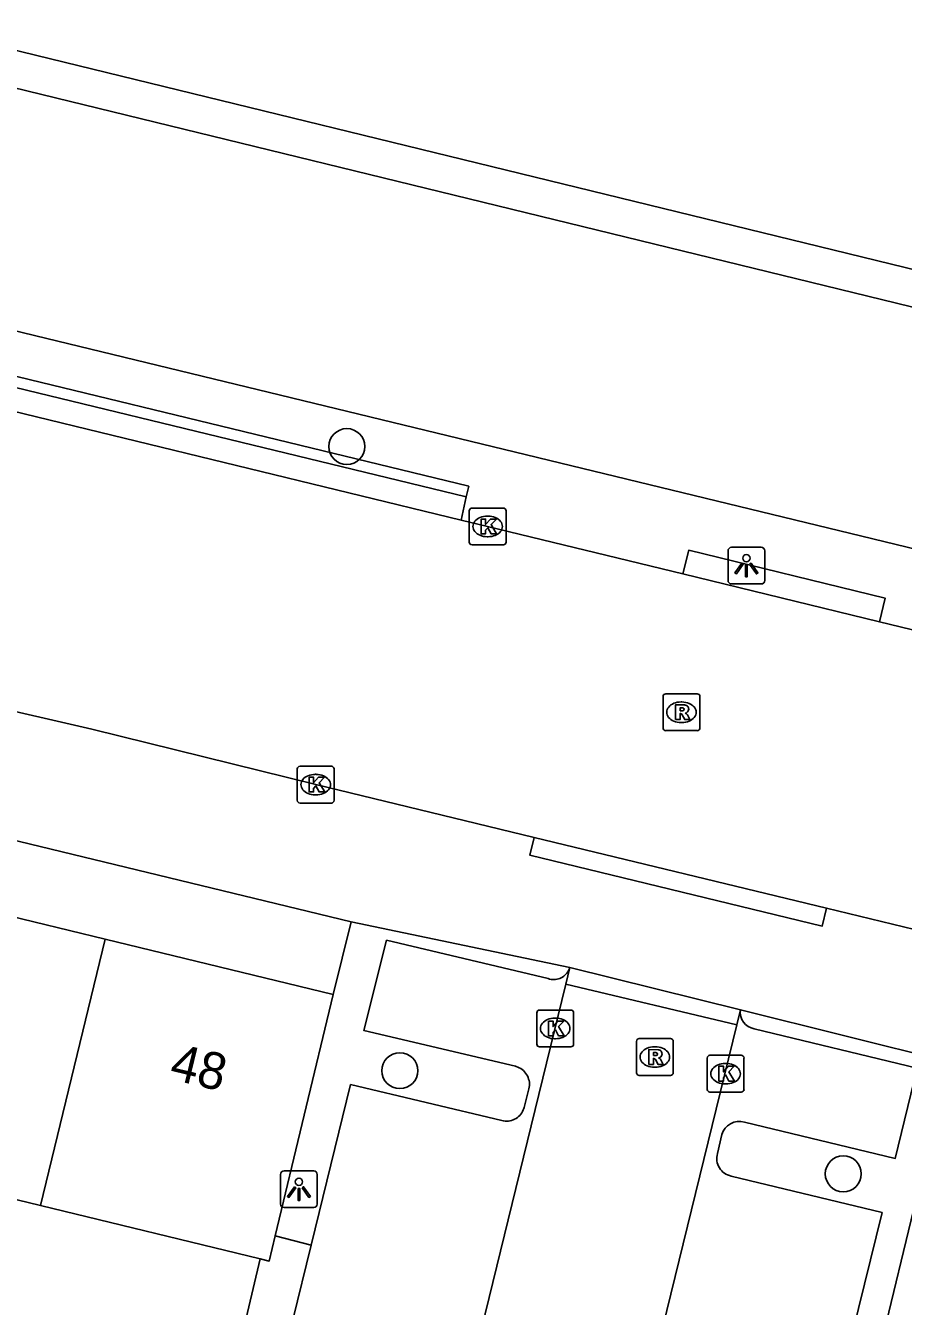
# Model space of a CAD drawing. Extents: x 162812 to 163818, y 381639 to 382470.
# Drawn here: x 163376.49 to 163400.35, y 382263.66 to 382298.47 of the extents above; entities that cross this region are included whole.
import ezdxf

# ---------------------------------------------------------------- set-up
doc = ezdxf.new("R2010")
doc.units = 0
for name, color, linetype in [('IMGEO_Boom', 7, 'Continuous'), ('IMGEO_Groenvoorziening', 7, 'Continuous'), ('IMGEO_Haag', 7, 'Continuous'), ('IMGEO_Kolk', 7, 'Continuous'), ('IMGEO_Lichtpunt', 7, 'Continuous'), ('IMGEO_Muur', 7, 'Continuous'), ('IMGEO_Pand', 7, 'Continuous'), ('IMGEO_Pand_nummerreeks', 7, 'Continuous'), ('IMGEO_Rijbaan_lokaal_gesloten', 7, 'Continuous'), ('IMGEO_Rijbaan_lokaal_open', 7, 'Continuous'), ('IMGEO_Rioolput', 7, 'Continuous'), ('IMGEO_Voetpad_open', 7, 'Continuous'), ('IMGEO_Waterloop', 7, 'Continuous')]:
    doc.layers.add(name, color=color, linetype=linetype)

msp = doc.modelspace()

# ---------------------------------------------------------------- linework, layer by layer
at = {"layer": 'IMGEO_Boom'}
for centre in [(163385.22, 382287.025), (163386.664, 382270.064), (163398.72, 382267.262)]:
    msp.add_circle(centre, 0.489, dxfattribs=at)
at = {"layer": 'IMGEO_Groenvoorziening'}
for points in [[(163321.09, 382310.224), (163499.763, 382266.618), (163515.133, 382262.867)], [(163454.527, 382271.183), (163319.582, 382303.902)], [(163388.463, 382285.657), (163388.534, 382285.949), (163352.363, 382294.719), (163352.293, 382294.427)], [(163399.704, 382282.265), (163399.86, 382282.905), (163394.518, 382284.21), (163394.36, 382283.564)]]:
    msp.add_lwpolyline(points, dxfattribs=at)
at = {"layer": 'IMGEO_Haag'}
for points in [[(163352.293, 382294.427), (163388.463, 382285.657)], [(163388.331, 382285.029), (163388.463, 382285.657)]]:
    msp.add_lwpolyline(points, dxfattribs=at)
at = {"layer": 'IMGEO_Kolk'}
for p, q in [((163388.625, 382285.355), (163389.477, 382285.355)), ((163388.55, 382284.429), (163388.55, 382285.281)), ((163389.038, 382285.135), (163389.063, 382285.135)), ((163389.551, 382285.281), (163389.551, 382284.429)), ((163389.477, 382284.355), (163388.625, 382284.355)), ((163389.061, 382284.575), (163389.036, 382284.575)), ((163383.874, 382277.412), (163383.874, 382278.264)), ((163383.949, 382278.338), (163384.801, 382278.338)), ((163384.362, 382278.118), (163384.387, 382278.118)), ((163384.875, 382278.264), (163384.875, 382277.412)), ((163384.801, 382277.338), (163383.949, 382277.338)), ((163384.385, 382277.558), (163384.36, 382277.558)), ((163390.386, 382270.786), (163390.386, 382271.638)), ((163390.461, 382271.712), (163391.313, 382271.712)), ((163390.874, 382271.492), (163390.899, 382271.492)), ((163391.387, 382271.638), (163391.387, 382270.786)), ((163391.313, 382270.712), (163390.461, 382270.712)), ((163390.897, 382270.932), (163390.872, 382270.932)), ((163395.019, 382269.556), (163395.019, 382270.408)), ((163395.094, 382270.482), (163395.946, 382270.482)), ((163396.02, 382270.408), (163396.02, 382269.556)), ((163395.507, 382270.262), (163395.532, 382270.262)), ((163395.53, 382269.702), (163395.505, 382269.702)), ((163395.946, 382269.482), (163395.094, 382269.482))]:
    msp.add_line(p, q, dxfattribs=at)
for points in [[(163388.625, 382285.355), (163389.477, 382285.355)], [(163388.55, 382284.429), (163388.55, 382285.281)], [(163388.871, 382285.055), (163388.994, 382285.055), (163388.994, 382284.904), (163389.124, 382285.055), (163389.288, 382285.055), (163389.142, 382284.904), (163389.295, 382284.655), (163389.143, 382284.655), (163389.058, 382284.819), (163388.994, 382284.752), (163388.994, 382284.655), (163388.871, 382284.655), (163388.871, 382285.055)], [(163389.551, 382285.281), (163389.551, 382284.429)], [(163389.477, 382284.355), (163388.625, 382284.355)], [(163383.874, 382277.412), (163383.874, 382278.264)], [(163383.949, 382278.338), (163384.801, 382278.338)], [(163384.195, 382278.038), (163384.318, 382278.038), (163384.318, 382277.887), (163384.448, 382278.038), (163384.612, 382278.038), (163384.466, 382277.887), (163384.619, 382277.638), (163384.467, 382277.638), (163384.382, 382277.802), (163384.318, 382277.735), (163384.318, 382277.638), (163384.195, 382277.638), (163384.195, 382278.038)], [(163384.875, 382278.264), (163384.875, 382277.412)], [(163384.801, 382277.338), (163383.949, 382277.338)], [(163390.386, 382270.786), (163390.386, 382271.638)], [(163390.461, 382271.712), (163391.313, 382271.712)], [(163390.707, 382271.412), (163390.83, 382271.412), (163390.83, 382271.261), (163390.96, 382271.412), (163391.124, 382271.412), (163390.978, 382271.261), (163391.131, 382271.012), (163390.979, 382271.012), (163390.894, 382271.176), (163390.83, 382271.109), (163390.83, 382271.012), (163390.707, 382271.012), (163390.707, 382271.412)], [(163391.387, 382271.638), (163391.387, 382270.786)], [(163391.313, 382270.712), (163390.461, 382270.712)], [(163395.019, 382269.556), (163395.019, 382270.408)], [(163395.094, 382270.482), (163395.946, 382270.482)], [(163396.02, 382270.408), (163396.02, 382269.556)], [(163395.34, 382270.182), (163395.463, 382270.182), (163395.463, 382270.031), (163395.593, 382270.182), (163395.757, 382270.182), (163395.611, 382270.031), (163395.764, 382269.782), (163395.612, 382269.782), (163395.527, 382269.946), (163395.463, 382269.879), (163395.463, 382269.782), (163395.34, 382269.782), (163395.34, 382270.182)], [(163395.946, 382269.482), (163395.094, 382269.482)]]:
    msp.add_lwpolyline(points, dxfattribs=at)
for centre, start, end in [((163388.627, 382285.279), 91.552, 178.448), ((163388.627, 382285.279), 91.552, 178.448), ((163389.475, 382285.279), 1.552, 88.448), ((163389.475, 382285.279), 1.552, 88.448), ((163388.627, 382284.431), 181.552, 268.448), ((163388.627, 382284.431), 181.552, 268.448), ((163389.475, 382284.431), 271.552, 358.448), ((163389.475, 382284.431), 271.552, 358.448), ((163383.951, 382278.262), 91.552, 178.448), ((163383.951, 382278.262), 91.552, 178.448), ((163384.799, 382278.262), 1.552, 88.448), ((163384.799, 382278.262), 1.552, 88.448), ((163383.951, 382277.414), 181.552, 268.448), ((163383.951, 382277.414), 181.552, 268.448), ((163384.799, 382277.414), 271.552, 358.448), ((163384.799, 382277.414), 271.552, 358.448), ((163390.463, 382271.636), 91.552, 178.448), ((163390.463, 382271.636), 91.552, 178.448), ((163391.311, 382271.636), 1.552, 88.448), ((163391.311, 382271.636), 1.552, 88.448), ((163390.463, 382270.788), 181.552, 268.448), ((163390.463, 382270.788), 181.552, 268.448), ((163391.311, 382270.788), 271.552, 358.448), ((163391.311, 382270.788), 271.552, 358.448), ((163395.096, 382270.406), 91.552, 178.448), ((163395.096, 382270.406), 91.552, 178.448), ((163395.944, 382270.406), 1.552, 88.448), ((163395.944, 382270.406), 1.552, 88.448), ((163395.096, 382269.558), 181.552, 268.448), ((163395.096, 382269.558), 181.552, 268.448), ((163395.944, 382269.558), 271.552, 358.448), ((163395.944, 382269.558), 271.552, 358.448)]:
    msp.add_arc(centre, 0.0765, start, end, dxfattribs=at)
for centre, major_axis, ratio, start_param, end_param in [((163389.037, 382284.855), (-0.387, 0.002), 0.722429, 4.712389, 7.853982), ((163389.062, 382284.855), (-0.39, 0.002), 0.717154, 1.570796, 4.712389), ((163384.361, 382277.838), (-0.387, 0.002), 0.722429, 4.712389, 7.853982), ((163384.386, 382277.838), (-0.39, 0.002), 0.717154, 1.570796, 4.712389), ((163390.873, 382271.212), (-0.387, 0.002), 0.722429, 4.712389, 7.853982), ((163390.898, 382271.212), (-0.39, 0.002), 0.717154, 1.570796, 4.712389), ((163395.506, 382269.982), (-0.387, 0.002), 0.722429, 4.712389, 7.853982), ((163395.531, 382269.982), (-0.39, 0.002), 0.717154, 1.570796, 4.712389)]:
    msp.add_ellipse(centre, major_axis=major_axis, ratio=ratio, start_param=start_param, end_param=end_param, dxfattribs=at)
at = {"layer": 'IMGEO_Lichtpunt'}
for p, q in [((163396.489, 382284.288), (163395.681, 382284.288)), ((163396.489, 382284.288), (163395.681, 382284.288)), ((163395.587, 382284.193), (163395.587, 382283.386)), ((163395.587, 382284.193), (163395.587, 382283.386)), ((163396.583, 382283.386), (163396.583, 382284.193)), ((163396.583, 382283.386), (163396.583, 382284.193)), ((163395.681, 382283.292), (163396.489, 382283.292)), ((163395.681, 382283.292), (163396.489, 382283.292)), ((163383.42, 382267.246), (163383.42, 382266.439)), ((163383.42, 382267.246), (163383.42, 382266.439)), ((163384.322, 382267.341), (163383.514, 382267.341)), ((163384.322, 382267.341), (163383.514, 382267.341)), ((163384.416, 382266.439), (163384.416, 382267.246)), ((163384.416, 382266.439), (163384.416, 382267.246)), ((163383.514, 382266.345), (163384.322, 382266.345)), ((163383.514, 382266.345), (163384.322, 382266.345))]:
    msp.add_line(p, q, dxfattribs=at)
for points in [[(163395.961, 382283.857), (163396, 382283.829), (163395.812, 382283.567), (163395.774, 382283.594), (163395.961, 382283.857)], [(163396.063, 382283.809), (163396.11, 382283.809), (163396.11, 382283.487), (163396.063, 382283.487), (163396.063, 382283.809)], [(163396.173, 382283.829), (163396.211, 382283.856), (163396.398, 382283.594), (163396.359, 382283.566), (163396.173, 382283.829)], [(163383.794, 382266.91), (163383.833, 382266.882), (163383.645, 382266.62), (163383.607, 382266.647), (163383.794, 382266.91)], [(163384.006, 382266.882), (163384.044, 382266.909), (163384.231, 382266.647), (163384.192, 382266.619), (163384.006, 382266.882)], [(163383.896, 382266.862), (163383.943, 382266.862), (163383.943, 382266.54), (163383.896, 382266.54), (163383.896, 382266.862)]]:
    msp.add_lwpolyline(points, dxfattribs=at)
for centre in [(163396.086, 382283.991), (163383.919, 382267.044)]:
    msp.add_circle(centre, 0.0994, dxfattribs=at)
for centre, start, end in [((163395.681, 382284.193), 90, 180), ((163395.681, 382284.193), 90, 180), ((163396.489, 382284.193), 0, 90), ((163396.489, 382284.193), 0, 90), ((163395.681, 382283.386), 180, 270), ((163395.681, 382283.386), 180, 270), ((163396.489, 382283.386), 270, 0), ((163396.489, 382283.386), 270, 360), ((163383.514, 382267.246), 90, 180), ((163383.514, 382267.246), 90, 180), ((163384.322, 382267.246), 0, 90), ((163384.322, 382267.246), 0, 90), ((163383.514, 382266.439), 180, 270), ((163383.514, 382266.439), 180, 270), ((163384.322, 382266.439), 270, 0), ((163384.322, 382266.439), 270, 360)]:
    msp.add_arc(centre, 0.0946, start, end, dxfattribs=at)
at = {"layer": 'IMGEO_Muur'}
msp.add_lwpolyline([(163319.582, 382303.902), (163454.527, 382271.183)], dxfattribs=at)
at = {"layer": 'IMGEO_Pand'}
for points in [[(163378.653, 382273.636), (163372.818, 382275.049)], [(163378.653, 382273.636), (163376.89, 382266.397)], [(163384.852, 382272.135), (163378.653, 382273.636)], [(163384.852, 382272.135), (163383.274, 382265.571)], [(163399.348, 382260.994), (163401.1, 382268.221)], [(163376.89, 382266.397), (163371.056, 382267.81)], [(163382.868, 382264.95), (163376.89, 382266.397)], [(163382.868, 382264.95), (163383.11, 382264.891), (163383.274, 382265.571)]]:
    msp.add_lwpolyline(points, dxfattribs=at)
at = {"layer": 'IMGEO_Rijbaan_lokaal_gesloten'}
for points in [[(163388.331, 382285.029), (163373.046, 382288.743), (163370.856, 382289.256), (163354.078, 382293.252), (163352.124, 382293.728)], [(163390.314, 382276.403), (163384.375, 382277.84), (163378.286, 382279.347), (163372.221, 382280.741), (163351.77, 382285.731), (163346.697, 382286.96)], [(163394.36, 382283.564), (163389.05, 382284.854), (163388.331, 382285.029)], [(163399.704, 382282.265), (163394.36, 382283.564)], [(163405.534, 382280.849), (163405.051, 382280.966), (163399.704, 382282.265)], [(163390.314, 382276.403), (163398.267, 382274.48)], [(163438.927, 382264.675), (163437.438, 382265.042), (163421.253, 382268.955), (163404.245, 382273.034), (163398.267, 382274.48)]]:
    msp.add_lwpolyline(points, dxfattribs=at)
at = {"layer": 'IMGEO_Rijbaan_lokaal_open'}
for points in [[(163391.174, 382272.417), (163386.793, 382254.498)], [(163395.824, 382271.309), (163391.174, 382272.417)], [(163392.351, 382257.15), (163395.824, 382271.309)]]:
    msp.add_lwpolyline(points, dxfattribs=at)
at = {"layer": 'IMGEO_Rioolput'}
for p, q in [((163393.82, 382279.379), (163393.82, 382280.231)), ((163393.895, 382280.305), (163394.747, 382280.305)), ((163394.821, 382280.231), (163394.821, 382279.379)), ((163394.308, 382280.085), (163394.333, 382280.085)), ((163394.331, 382279.525), (163394.306, 382279.525)), ((163394.747, 382279.305), (163393.895, 382279.305)), ((163393.095, 382270.009), (163393.095, 382270.861)), ((163393.17, 382270.935), (163394.022, 382270.935)), ((163393.583, 382270.715), (163393.608, 382270.715)), ((163394.096, 382270.861), (163394.096, 382270.009)), ((163393.606, 382270.155), (163393.581, 382270.155)), ((163394.022, 382269.935), (163393.17, 382269.935))]:
    msp.add_line(p, q, dxfattribs=at)
for points in [[(163393.82, 382279.379), (163393.82, 382280.231)], [(163393.895, 382280.305), (163394.747, 382280.305)], [(163394.821, 382280.231), (163394.821, 382279.379)], [(163394.409, 382280.003), (163394.157, 382280.005), (163394.157, 382279.605)], [(163394.157, 382279.605), (163394.281, 382279.605), (163394.281, 382279.767), (163394.292, 382279.767)], [(163394.335, 382279.924), (163394.281, 382279.924), (163394.281, 382279.843)], [(163394.281, 382279.843), (163394.333, 382279.843)], [(163394.339, 382279.738), (163394.41, 382279.605), (163394.55, 382279.605), (163394.485, 382279.731)], [(163394.747, 382279.305), (163393.895, 382279.305)], [(163393.095, 382270.009), (163393.095, 382270.861)], [(163393.17, 382270.935), (163394.022, 382270.935)], [(163394.096, 382270.861), (163394.096, 382270.009)], [(163393.684, 382270.633), (163393.432, 382270.635), (163393.432, 382270.235)], [(163393.432, 382270.235), (163393.556, 382270.235), (163393.556, 382270.397), (163393.567, 382270.397)], [(163393.61, 382270.554), (163393.556, 382270.554), (163393.556, 382270.473)], [(163393.556, 382270.473), (163393.608, 382270.473)], [(163393.614, 382270.368), (163393.685, 382270.235), (163393.825, 382270.235), (163393.76, 382270.361)], [(163394.022, 382269.935), (163393.17, 382269.935)]]:
    msp.add_lwpolyline(points, dxfattribs=at)
for centre, radius, start, end in [((163393.897, 382280.229), 0.0765, 91.552, 178.448), ((163393.897, 382280.229), 0.0765, 91.552, 178.448), ((163394.745, 382280.229), 0.0765, 1.552, 88.448), ((163394.745, 382280.229), 0.0765, 1.552, 88.448), ((163394.291, 382279.714), 0.0533, 26.0293, 88.6989), ((163394.317, 382280.032), 0.19, 274.7715, 282.9687), ((163394.341, 382279.828), 0.0964, 77.0061, 93.1865), ((163394.355, 382279.885), 0.0378, 276.6634, 79.6772), ((163394.408, 382279.893), 0.109, 350.3612, 89.416), ((163394.406, 382279.893), 0.112, 277.5842, 350.9817), ((163394.39, 382279.678), 0.108, 29.5134, 73.7905), ((163393.897, 382279.381), 0.0765, 181.552, 268.448), ((163393.897, 382279.381), 0.0765, 181.552, 268.448), ((163394.745, 382279.381), 0.0765, 271.552, 358.448), ((163394.745, 382279.381), 0.0765, 271.552, 358.448), ((163393.172, 382270.859), 0.0765, 91.552, 178.448), ((163393.172, 382270.859), 0.0765, 91.552, 178.448), ((163394.02, 382270.859), 0.0765, 1.552, 88.448), ((163394.02, 382270.859), 0.0765, 1.552, 88.448), ((163393.566, 382270.344), 0.0533, 26.0293, 88.6989), ((163393.592, 382270.662), 0.19, 274.7715, 282.9687), ((163393.616, 382270.458), 0.0964, 77.0061, 93.1865), ((163393.63, 382270.515), 0.0378, 276.6634, 79.6772), ((163393.683, 382270.523), 0.109, 350.3612, 89.416), ((163393.681, 382270.523), 0.112, 277.5842, 350.9817), ((163393.665, 382270.308), 0.108, 29.5134, 73.7905), ((163393.172, 382270.011), 0.0765, 181.552, 268.448), ((163393.172, 382270.011), 0.0765, 181.552, 268.448), ((163394.02, 382270.011), 0.0765, 271.552, 358.448), ((163394.02, 382270.011), 0.0765, 271.552, 358.448)]:
    msp.add_arc(centre, radius, start, end, dxfattribs=at)
for centre, major_axis, ratio, start_param, end_param in [((163394.307, 382279.805), (-0.387, 0.002), 0.722429, 4.712389, 7.853982), ((163394.332, 382279.805), (-0.39, 0.002), 0.717154, 1.570796, 4.712389), ((163393.582, 382270.435), (-0.387, 0.002), 0.722429, 4.712389, 7.853982), ((163393.607, 382270.435), (-0.39, 0.002), 0.717154, 1.570796, 4.712389)]:
    msp.add_ellipse(centre, major_axis=major_axis, ratio=ratio, start_param=start_param, end_param=end_param, dxfattribs=at)
at = {"layer": 'IMGEO_Voetpad_open'}
for points in [[(163350.348, 382282.582), (163385.343, 382274.108)], [(163398.267, 382274.48), (163398.15, 382273.995), (163390.197, 382275.918), (163390.314, 382276.403)], [(163385.343, 382274.108), (163384.852, 382272.135)], [(163391.282, 382272.872), (163385.343, 382274.108)], [(163384.25, 382265.324), (163385.325, 382269.688), (163389.436, 382268.706), (163389.48, 382268.697), (163389.524, 382268.692), (163389.568, 382268.69), (163389.613, 382268.693), (163389.656, 382268.7), (163389.7, 382268.71), (163389.742, 382268.725), (163389.782, 382268.743), (163389.821, 382268.764), (163389.858, 382268.789), (163389.892, 382268.818), (163389.924, 382268.849), (163389.953, 382268.883), (163389.979, 382268.919), (163390.001, 382268.957), (163390.02, 382268.998), (163390.035, 382269.04), (163390.042, 382269.065), (163390.172, 382269.567), (163390.181, 382269.612), (163390.186, 382269.657), (163390.187, 382269.703), (163390.184, 382269.748), (163390.176, 382269.793), (163390.165, 382269.837), (163390.15, 382269.88), (163390.131, 382269.922), (163390.108, 382269.961), (163390.082, 382269.999), (163390.053, 382270.034), (163390.021, 382270.066), (163389.986, 382270.095), (163389.949, 382270.121), (163389.909, 382270.144), (163389.867, 382270.163), (163389.824, 382270.178), (163389.809, 382270.182), (163385.684, 382271.152), (163386.301, 382273.609), (163390.696, 382272.565), (163390.735, 382272.553), (163390.774, 382272.545), (163390.814, 382272.54), (163390.855, 382272.539), (163390.895, 382272.542), (163390.935, 382272.548), (163390.974, 382272.558), (163391.012, 382272.571), (163391.049, 382272.588), (163391.085, 382272.607), (163391.118, 382272.63), (163391.149, 382272.656), (163391.178, 382272.684), (163391.204, 382272.715), (163391.227, 382272.748), (163391.247, 382272.783), (163391.264, 382272.82), (163391.278, 382272.858), (163391.282, 382272.872)], [(163391.174, 382272.417), (163391.282, 382272.872)], [(163391.282, 382272.872), (163395.921, 382271.719)], [(163395.921, 382271.719), (163395.824, 382271.309)], [(163401.6, 382270.302), (163395.921, 382271.719)], [(163396.301, 382271.205), (163400.727, 382270.134), (163400.132, 382267.679), (163396.03, 382268.667)], [(163395.417, 382268.325), (163395.298, 382267.809)], [(163395.671, 382267.2), (163399.773, 382266.205), (163397.366, 382256.432), (163392.97, 382257.511)], [(163383.274, 382265.571), (163384.25, 382265.324)], [(163384.25, 382265.324), (163383.257, 382261.265)], [(163382.062, 382261.539), (163382.868, 382264.95)]]:
    msp.add_lwpolyline(points, dxfattribs=at)
for centre, radius, start, end in [((163396.37, 382271.654), 0.454, 171.7146, 261.2364), ((163395.895, 382268.189), 0.497, 74.1919, 164.1234), ((163395.771, 382267.68), 0.491, 164.7777, 258.1955)]:
    msp.add_arc(centre, radius, start, end, dxfattribs=at)
at = {"layer": 'IMGEO_Waterloop'}
msp.add_lwpolyline([(163515.373, 382263.837), (163500, 382267.589), (163321.322, 382311.196)], dxfattribs=at)

# ---------------------------------------------------------------- texts
at = {"layer": 'IMGEO_Pand_nummerreeks'}
msp.add_text('48', height=1, rotation=346.3879, dxfattribs=at).set_placement((163380.363, 382269.847))

doc.saveas('drawing.dxf')
